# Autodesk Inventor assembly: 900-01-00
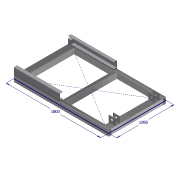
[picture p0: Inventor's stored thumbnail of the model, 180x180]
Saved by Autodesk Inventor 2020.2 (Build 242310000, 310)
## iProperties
Created: 2015-10
Part Number: 900-01-00
Document SubType Name: Konstrukcja spawana
Designer: F.Stasiak
Weld Material: Stal, miękka, spawana
Catalog Web Link: www.expertbooks.pl
Manager: www.cadconsulting.pl
Company: Fabian Stasiak CAD Consulting
_SolveAssemblyDoc: Frame Generator Solve Assembly
_Version: 15.0.0
Author: F.Stasiak
Subject: Zbiór ćwiczeń. Autodesk Inventor 2020. Kurs Professional
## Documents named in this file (7)
- C:\2020_Kurs_Professional\R3 Dynamika\Komponenty_dyn\900-01-00.iam
- C:\2020_Kurs_Professional\R3 Dynamika\Komponenty_dyn\900-01-00_Szkielet.ipt
- C:\2020_Kurs_Professional\R3 Dynamika\900-01\Frame\Frame_900_01_00.iam
- C:\2020_Kurs_Professional\R3 Dynamika\Komponenty_dyn\900-01-06.ipt
- C:\2020_Kurs_Professional\R3 Dynamika\Komponenty_dyn\900-01-07.ipt
- C:\2020_Kurs_Professional\R3 Dynamika\Komponenty_dyn\EN 10058 - 900-01-08.ipt
- C:\2020_Kurs_Professional\R3 Dynamika\Komponenty_dyn\900-01-08.ipt
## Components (12 placed, 6 different names)
1. 900-01-00_Szkielet:1
2. Frame_900_01_00:1 [sub-assembly] — Zestawiający:1, Równoległy:1, Równoległy:2, Zestawiający:2, Równoległy:3, Równoległy:4, Zestawiający:3, Równoległy:5, Zestawiający:4, Równoległy:7, Równoległy:8, Zestawiający:5, Zestawiający:7, Zestawiający:9, Równoległy:11, Zestawiający:10, Równoległy:14
3. 900-01-06:1 — Zestawiający:1, Równoległy:1, Równoległy:2, Równoległy:6, Równoległy:12, Zestawiający:11
4. 900-01-06:2 — Zestawiający:2, Równoległy:3, Równoległy:4, Równoległy:13, Równoległy:15, Równoległy:16, Równoległy:17
5. 900-01-07:1 — Zestawiający:3, Równoległy:5, Równoległy:6, Równoległy:9, Zestawiający:6
6. 900-01-07:2 — Zestawiający:4, Równoległy:7, Równoległy:8, Równoległy:10, Zestawiający:8
7. 900-01-07:3 — Zestawiający:5, Równoległy:9, Zestawiający:6
8. 900-01-07:4 — Zestawiający:7, Równoległy:10, Zestawiający:8
9. EN 10058 - 900-01-08:1 — Zestawiający:9, Równoległy:11, Równoległy:12, Równoległy:19
10. EN 10058 - 900-01-08:2 — Zestawiający:10, Równoległy:13, Równoległy:14
11. 900-01-08:1 — Równoległy:15, Równoległy:16, Równoległy:17, Równoległy:18
12. 900-01-08:2 — Zestawiający:11, Równoległy:18, Równoległy:19
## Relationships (30: Flush 19, Mate 11)
- Zestawiający:1 [Mate]: Frame_900_01_00:1 ↔ 900-01-06:1
- Równoległy:1 [Flush]: Frame_900_01_00:1 ↔ 900-01-06:1
- Równoległy:2 [Flush]: Frame_900_01_00:1 ↔ 900-01-06:1
- Zestawiający:2 [Mate]: Frame_900_01_00:1 ↔ 900-01-06:2
- Równoległy:3 [Flush]: Frame_900_01_00:1 ↔ 900-01-06:2
- Równoległy:4 [Flush]: Frame_900_01_00:1 ↔ 900-01-06:2
- Zestawiający:3 [Mate]: Frame_900_01_00:1 ↔ 900-01-07:1
- Równoległy:5 [Flush]: Frame_900_01_00:1 ↔ 900-01-07:1
- Równoległy:6 [Flush]: 900-01-06:1 ↔ 900-01-07:1
- Zestawiający:4 [Mate]: Frame_900_01_00:1 ↔ 900-01-07:2
- Równoległy:7 [Flush]: Frame_900_01_00:1 ↔ 900-01-07:2
- Równoległy:8 [Flush]: Frame_900_01_00:1 ↔ 900-01-07:2
- Zestawiający:5 [Mate]: Frame_900_01_00:1 ↔ 900-01-07:3
- Równoległy:9 [Flush]: 900-01-07:1 ↔ 900-01-07:3
- Zestawiający:6 [Mate]: 900-01-07:1 ↔ 900-01-07:3
- Zestawiający:7 [Mate]: Frame_900_01_00:1 ↔ 900-01-07:4
- Równoległy:10 [Flush]: 900-01-07:2 ↔ 900-01-07:4
- Zestawiający:8 [Mate]: 900-01-07:2 ↔ 900-01-07:4
- Zestawiający:9 [Mate]: Frame_900_01_00:1 ↔ EN 10058 - 900-01-08:1
- Równoległy:11 [Flush]: Frame_900_01_00:1 ↔ EN 10058 - 900-01-08:1
- Równoległy:12 [Flush]: 900-01-06:1 ↔ EN 10058 - 900-01-08:1
- Zestawiający:10 [Mate]: Frame_900_01_00:1 ↔ EN 10058 - 900-01-08:2
- Równoległy:13 [Flush]: 900-01-06:2 ↔ EN 10058 - 900-01-08:2
- Równoległy:14 [Flush]: Frame_900_01_00:1 ↔ EN 10058 - 900-01-08:2
- Równoległy:15 [Flush]: 900-01-06:2 ↔ 900-01-08:1
- Równoległy:16 [Flush]: 900-01-06:2 ↔ 900-01-08:1
- Równoległy:17 [Flush]: 900-01-06:2 ↔ 900-01-08:1
- Zestawiający:11 [Mate]: 900-01-06:1 ↔ 900-01-08:2
- Równoległy:18 [Flush]: 900-01-08:1 ↔ 900-01-08:2
- Równoległy:19 [Flush]: EN 10058 - 900-01-08:1 ↔ 900-01-08:2
